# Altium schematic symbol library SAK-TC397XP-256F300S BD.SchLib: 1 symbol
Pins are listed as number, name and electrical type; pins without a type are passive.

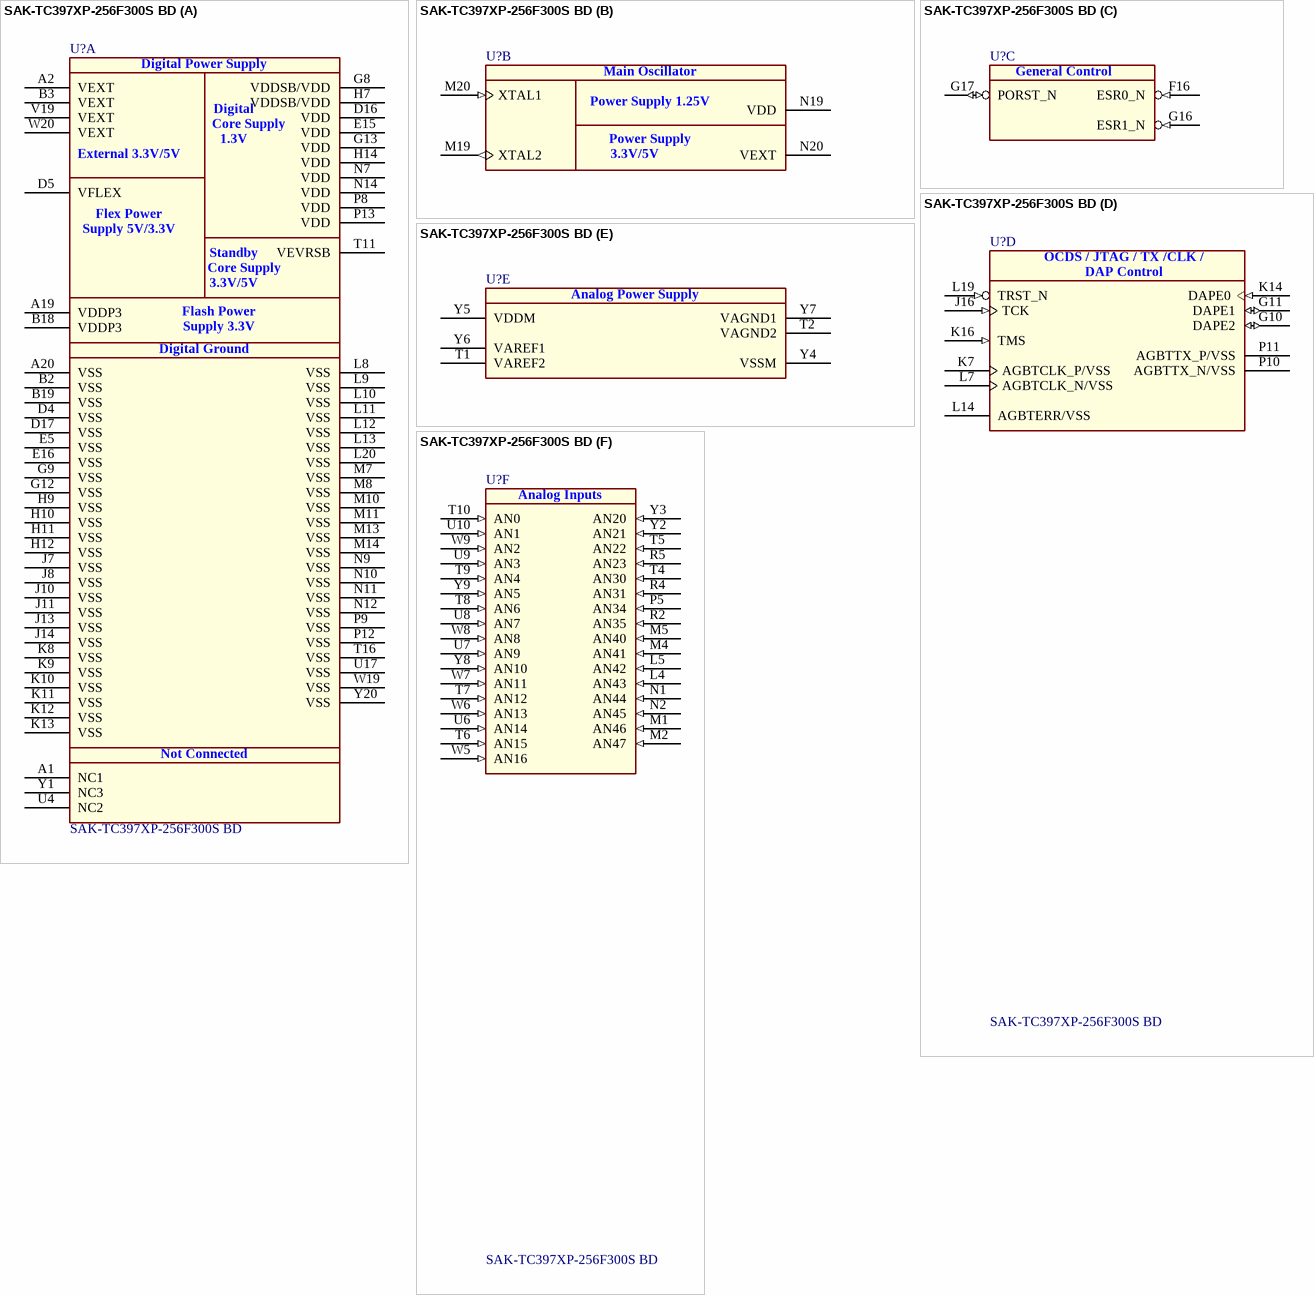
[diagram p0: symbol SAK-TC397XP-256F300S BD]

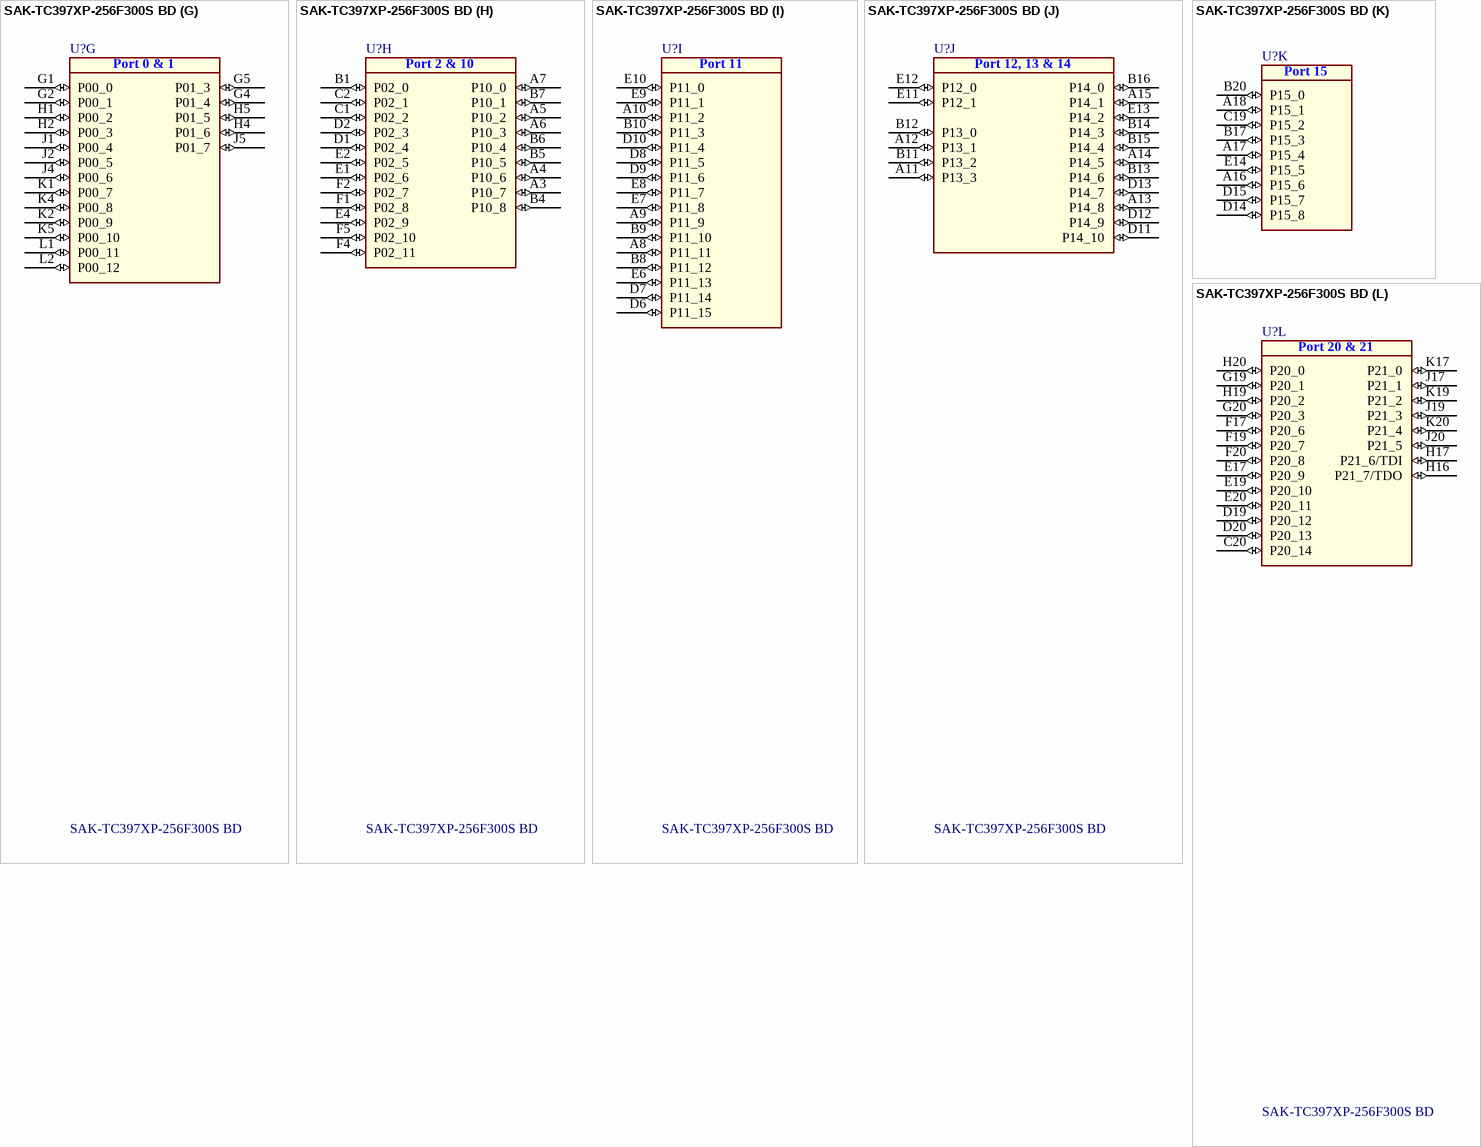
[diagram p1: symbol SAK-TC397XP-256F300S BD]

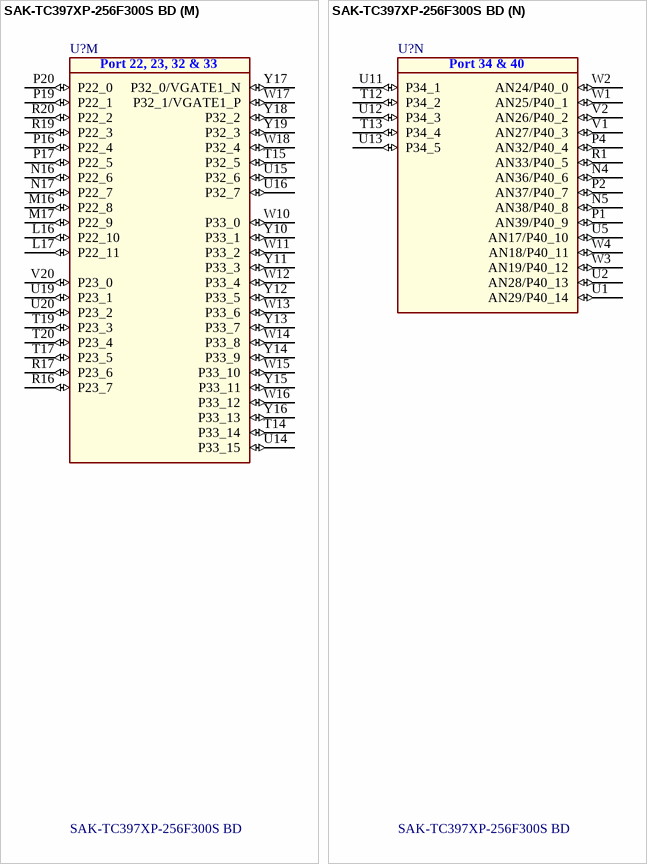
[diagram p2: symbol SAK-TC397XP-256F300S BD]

## SAK-TC397XP-256F300S BD
designator U?
32-Bit Single-Chip Microcontroller; Manufacturer: Infineon Technologies
part A pins: A1 NC1, A2 VEXT (power), A19 VDDP3 (power), A20 VSS (power), B2 VSS (power), B3 VEXT (power), B18 VDDP3 (power), B19 VSS (power), D4 VSS (power), D5 VFLEX (power), D16 VDD (power), D17 VSS (power), E5 VSS (power), E15 VDD (power), E16 VSS (power), G8 VDDSB/VDD (power), G9 VSS (power), G12 VSS (power), G13 VDD (power), H7 VDDSB/VDD (power), H9 VSS (power), H10 VSS (power), H11 VSS (power), H12 VSS (power), H14 VDD (power), J7 VSS (power), J8 VSS (power), J10 VSS (power), J11 VSS (power), J13 VSS (power), J14 VSS (power), K8 VSS (power), K9 VSS (power), K10 VSS (power), K11 VSS (power), K12 VSS (power), K13 VSS (power), L8 VSS (power), L9 VSS (power), L10 VSS (power), L11 VSS (power), L12 VSS (power), L13 VSS (power), L20 VSS (power), M7 VSS (power), M8 VSS (power), M10 VSS (power), M11 VSS (power), M13 VSS (power), M14 VSS (power), N7 VDD (power), N9 VSS (power), N10 VSS (power), N11 VSS (power), N12 VSS (power), N14 VDD (power), P8 VDD (power), P9 VSS (power), P12 VSS (power), P13 VDD (power), T11 VEVRSB (power), T16 VSS (power), U4 NC2, U17 VSS (power), V19 VEXT (power), W19 VSS (power), W20 VEXT (power), Y1 NC3, Y20 VSS (power)
part B pins: M19 XTAL2 (out), M20 XTAL1 (in), N19 VDD (power), N20 VEXT (power)
part C pins: F16 ESR0_N (in), G16 ESR1_N (in), G17 PORST_N (io)
part D pins: G10 DAPE2 (io), G11 DAPE1 (io), J16 TCK (in), K7 AGBTCLK_P/VSS (power), K14 DAPE0 (in), K16 TMS (in), L7 AGBTCLK_N/VSS (power), L14 AGBTERR/VSS (power), L19 TRST_N (in), P10 AGBTTX_N/VSS (power), P11 AGBTTX_P/VSS (power)
part E pins: T1 VAREF2 (power), T2 VAGND2 (power), Y4 VSSM (power), Y5 VDDM (power), Y6 VAREF1 (power), Y7 VAGND1 (power)
part F pins: L4 AN43 (in), L5 AN42 (in), M1 AN46 (in), M2 AN47 (in), M4 AN41 (in), M5 AN40 (in), N1 AN44 (in), N2 AN45 (in), P5 AN34 (in), R2 AN35 (in), R4 AN31 (in), R5 AN23 (in), T4 AN30 (in), T5 AN22 (in), T6 AN15 (in), T7 AN12 (in), T8 AN6 (in), T9 AN4 (in), T10 AN0 (in), U6 AN14 (in), U7 AN9 (in), U8 AN7 (in), U9 AN3 (in), U10 AN1 (in), W5 AN16 (in), W6 AN13 (in), W7 AN11 (in), W8 AN8 (in), W9 AN2 (in), Y2 AN21 (in), Y3 AN20 (in), Y8 AN10 (in), Y9 AN5 (in)
part G pins: G1 P00_0 (io), G2 P00_1 (io), G4 P01_4 (io), G5 P01_3 (io), H1 P00_2 (io), H2 P00_3 (io), H4 P01_6 (io), H5 P01_5 (io), J1 P00_4 (io), J2 P00_5 (io), J4 P00_6 (io), J5 P01_7 (io), K1 P00_7 (io), K2 P00_9 (io), K4 P00_8 (io), K5 P00_10 (io), L1 P00_11 (io), L2 P00_12 (io)
part H pins: A3 P10_7 (io), A4 P10_6 (io), A5 P10_2 (io), A6 P10_3 (io), A7 P10_0 (io), B1 P02_0 (io), B4 P10_8 (io), B5 P10_5 (io), B6 P10_4 (io), B7 P10_1 (io), C1 P02_2 (io), C2 P02_1 (io), D1 P02_4 (io), D2 P02_3 (io), E1 P02_6 (io), E2 P02_5 (io), E4 P02_9 (io), F1 P02_8 (io), F2 P02_7 (io), F4 P02_11 (io), F5 P02_10 (io)
part I pins: A8 P11_11 (io), A9 P11_9 (io), A10 P11_2 (io), B8 P11_12 (io), B9 P11_10 (io), B10 P11_3 (io), D6 P11_15 (io), D7 P11_14 (io), D8 P11_5 (io), D9 P11_6 (io), D10 P11_4 (io), E6 P11_13 (io), E7 P11_8 (io), E8 P11_7 (io), E9 P11_1 (io), E10 P11_0 (io)
part J pins: A11 P13_3 (io), A12 P13_1 (io), A13 P14_8 (io), A14 P14_5 (io), A15 P14_1 (io), B11 P13_2 (io), B12 P13_0 (io), B13 P14_6 (io), B14 P14_3 (io), B15 P14_4 (io), B16 P14_0 (io), D11 P14_10 (io), D12 P14_9 (io), D13 P14_7 (io), E11 P12_1 (io), E12 P12_0 (io), E13 P14_2 (io)
part K pins: A16 P15_6 (io), A17 P15_4 (io), A18 P15_1 (io), B17 P15_3 (io), B20 P15_0 (io), C19 P15_2 (io), D14 P15_8 (io), D15 P15_7 (io), E14 P15_5 (io)
part L pins: C20 P20_14 (io), D19 P20_12 (io), D20 P20_13 (io), E17 P20_9 (io), E19 P20_10 (io), E20 P20_11 (io), F17 P20_6 (io), F19 P20_7 (io), F20 P20_8 (io), G19 P20_1 (io), G20 P20_3 (io), H16 P21_7/TDO (io), H17 P21_6/TDI (io), H19 P20_2 (io), H20 P20_0 (io), J17 P21_1 (io), J19 P21_3 (io), J20 P21_5 (io), K17 P21_0 (io), K19 P21_2 (io), K20 P21_4 (io)
part M pins: L16 P22_10 (io), L17 P22_11 (io), M16 P22_8 (io), M17 P22_9 (io), N16 P22_6 (io), N17 P22_7 (io), P16 P22_4 (io), P17 P22_5 (io), P19 P22_1 (io), P20 P22_0 (io), R16 P23_7 (io), R17 P23_6 (io), R19 P22_3 (io), R20 P22_2 (io), T14 P33_14 (io), T15 P32_5 (io), T17 P23_5 (io), T19 P23_3 (io), T20 P23_4 (io), U14 P33_15 (io), U15 P32_6 (io), U16 P32_7 (io), U19 P23_1 (io), U20 P23_2 (io), V20 P23_0 (io), W10 P33_0 (io), W11 P33_2 (io), W12 P33_4 (io), W13 P33_6 (io), W14 P33_8 (io), W15 P33_10 (io), W16 P33_12 (io), W17 P32_1/VGATE1_P (io), W18 P32_4 (io), Y10 P33_1 (io), Y11 P33_3 (io), Y12 P33_5 (io), Y13 P33_7 (io), Y14 P33_9 (io), Y15 P33_11 (io), Y16 P33_13 (io), Y17 P32_0/VGATE1_N (io), Y18 P32_2 (io), Y19 P32_3 (io)
part N pins: N4 AN36/P40_6 (io), N5 AN38/P40_8 (io), P1 AN39/P40_9 (io), P2 AN37/P40_7 (io), P4 AN32/P40_4 (io), R1 AN33/P40_5 (io), T12 P34_2 (io), T13 P34_4 (io), U1 AN29/P40_14 (io), U2 AN28/P40_13 (io), U5 AN17/P40_10 (io), U11 P34_1 (io), U12 P34_3 (io), U13 P34_5 (io), V1 AN27/P40_3 (io), V2 AN26/P40_2 (io), W1 AN25/P40_1 (io), W2 AN24/P40_0 (io), W3 AN19/P40_12 (io), W4 AN18/P40_11 (io)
